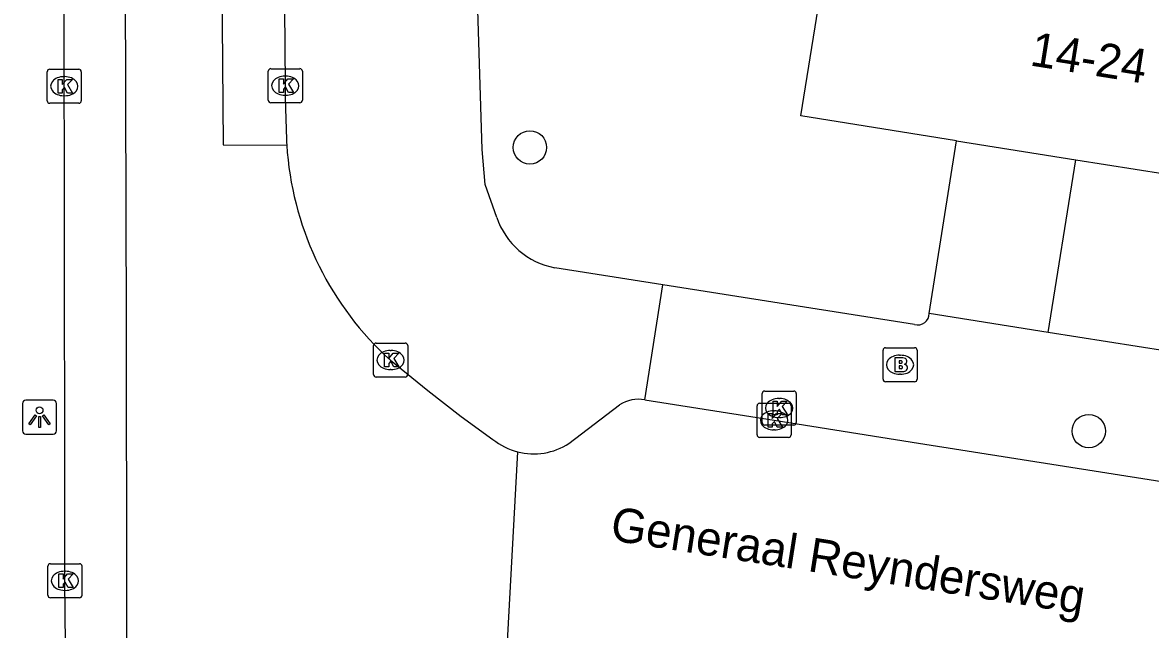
# Model space of a CAD drawing. Extents: x 161084 to 161928, y 385355 to 386522.
# Drawn here: x 161636.34 to 161669.44, y 385406.41 to 385424.21 of the extents above; entities that cross this region are included whole.
import ezdxf

# ---------------------------------------------------------------- set-up
doc = ezdxf.new("R2010")
doc.units = 0
for name, color, linetype in [('IMGEO_Boom', 7, 'Continuous'), ('IMGEO_Brandkraan', 7, 'Continuous'), ('IMGEO_Fietspad_gesloten', 7, 'Continuous'), ('IMGEO_Kolk', 7, 'Continuous'), ('IMGEO_Lichtpunt', 7, 'Continuous'), ('IMGEO_Openbare_ruimte_label', 7, 'Continuous'), ('IMGEO_Pand', 7, 'Continuous'), ('IMGEO_Pand_nummerreeks', 7, 'Continuous'), ('IMGEO_Rijbaan_lokaal_gesloten', 7, 'Continuous'), ('IMGEO_Rijbaan_lokaal_open', 7, 'Continuous'), ('IMGEO_Voetpad_open', 7, 'Continuous')]:
    doc.layers.add(name, color=color, linetype=linetype)

msp = doc.modelspace()

# ---------------------------------------------------------------- linework, layer by layer
at = {"layer": 'IMGEO_Boom'}
for centre in [(161651.233, 385420.546), (161667.63, 385412.225)]:
    msp.add_circle(centre, 0.489, dxfattribs=at)
at = {"layer": 'IMGEO_Brandkraan'}
for p, q in [((161661.594, 385413.744), (161661.594, 385414.596)), ((161661.669, 385414.67), (161662.521, 385414.67)), ((161662.082, 385414.45), (161662.107, 385414.45)), ((161662.595, 385414.596), (161662.595, 385413.744)), ((161662.105, 385413.89), (161662.08, 385413.89)), ((161662.521, 385413.67), (161661.669, 385413.67))]:
    msp.add_line(p, q, dxfattribs=at)
for points in [[(161661.594, 385413.744), (161661.594, 385414.596)], [(161661.669, 385414.67), (161662.521, 385414.67)], [(161661.942, 385414.37), (161661.942, 385413.97), (161662.155, 385413.97)], [(161662.173, 385414.37), (161661.942, 385414.37)], [(161662.595, 385414.596), (161662.595, 385413.744)], [(161662.121, 385414.289), (161662.067, 385414.289), (161662.067, 385414.213)], [(161662.067, 385414.213), (161662.12, 385414.213)], [(161662.129, 385414.137), (161662.067, 385414.137), (161662.067, 385414.056)], [(161662.067, 385414.056), (161662.129, 385414.056)], [(161662.521, 385413.67), (161661.669, 385413.67)]]:
    msp.add_lwpolyline(points, dxfattribs=at)
for centre, radius, start, end in [((161661.671, 385414.594), 0.0765, 91.552, 178.448), ((161661.671, 385414.594), 0.0765, 91.552, 178.448), ((161662.177, 385414.225), 0.145, 59.4692, 91.5367), ((161662.519, 385414.594), 0.0765, 1.552, 88.448), ((161662.519, 385414.594), 0.0765, 1.552, 88.448), ((161662.122, 385414.251), 0.0379, 267.8285, 90.9355), ((161662.13, 385414.096), 0.0404, 269.8759, 90.5077), ((161662.202, 385414.272), 0.0922, 285.5137, 58.1501), ((161662.207, 385414.08), 0.105, 301.3115, 78.989), ((161661.671, 385413.746), 0.0765, 181.552, 268.448), ((161661.671, 385413.746), 0.0765, 181.552, 268.448), ((161662.161, 385414.221), 0.251, 268.6676, 293.5347), ((161662.519, 385413.746), 0.0765, 271.552, 358.448), ((161662.519, 385413.746), 0.0765, 271.552, 358.448)]:
    msp.add_arc(centre, radius, start, end, dxfattribs=at)
for centre, major_axis, ratio, start_param, end_param in [((161662.081, 385414.17), (-0.387, 0.002), 0.722429, 4.712389, 7.853982), ((161662.106, 385414.17), (-0.39, 0.002), 0.717154, 1.570796, 4.712389)]:
    msp.add_ellipse(centre, major_axis=major_axis, ratio=ratio, start_param=start_param, end_param=end_param, dxfattribs=at)
at = {"layer": 'IMGEO_Fietspad_gesloten'}
for points in [[(161637.604, 385404.614), (161637.589, 385404.787), (161637.6, 385405.961), (161637.587, 385407.832), (161637.573, 385420.761), (161637.56, 385421.972), (161637.567, 385422.343), (161637.552, 385439.789), (161637.549, 385442.052)], [(161643.92, 385441.991), (161643.912, 385441.776), (161643.897, 385440.551), (161644.054, 385422.357), (161644.051, 385421.992), (161644.086, 385420.778), (161644.09, 385420.697), (161644.095, 385420.617)]]:
    msp.add_lwpolyline(points, dxfattribs=at)
at = {"layer": 'IMGEO_Kolk'}
for p, q in [((161637.066, 385421.917), (161637.066, 385422.769)), ((161637.141, 385422.843), (161637.993, 385422.843)), ((161638.067, 385422.769), (161638.067, 385421.917)), ((161643.553, 385421.931), (161643.553, 385422.783)), ((161643.628, 385422.857), (161644.48, 385422.857)), ((161644.041, 385422.637), (161644.066, 385422.637)), ((161644.554, 385422.783), (161644.554, 385421.931)), ((161637.554, 385422.623), (161637.579, 385422.623)), ((161637.577, 385422.063), (161637.552, 385422.063)), ((161644.064, 385422.077), (161644.039, 385422.077)), ((161637.993, 385421.843), (161637.141, 385421.843)), ((161644.48, 385421.857), (161643.628, 385421.857)), ((161646.644, 385413.881), (161646.644, 385414.733)), ((161646.719, 385414.807), (161647.571, 385414.807)), ((161647.645, 385414.733), (161647.645, 385413.881)), ((161647.132, 385414.587), (161647.157, 385414.587)), ((161647.155, 385414.027), (161647.13, 385414.027)), ((161647.571, 385413.807), (161646.719, 385413.807)), ((161658.121, 385413.399), (161658.973, 385413.399)), ((161657.973, 385413.041), (161658.825, 385413.041)), ((161658.046, 385412.473), (161658.046, 385413.325)), ((161658.534, 385413.179), (161658.559, 385413.179)), ((161659.047, 385413.325), (161659.047, 385412.473)), ((161657.898, 385412.115), (161657.898, 385412.967)), ((161658.386, 385412.821), (161658.411, 385412.821)), ((161658.899, 385412.967), (161658.899, 385412.115)), ((161658.973, 385412.399), (161658.121, 385412.399)), ((161658.557, 385412.619), (161658.532, 385412.619)), ((161658.825, 385412.041), (161657.973, 385412.041)), ((161658.409, 385412.261), (161658.384, 385412.261)), ((161637.086, 385407.406), (161637.086, 385408.258)), ((161637.161, 385408.332), (161638.013, 385408.332)), ((161637.574, 385408.112), (161637.599, 385408.112)), ((161638.087, 385408.258), (161638.087, 385407.406)), ((161637.597, 385407.552), (161637.572, 385407.552)), ((161638.013, 385407.332), (161637.161, 385407.332))]:
    msp.add_line(p, q, dxfattribs=at)
for points in [[(161637.066, 385421.917), (161637.066, 385422.769)], [(161637.141, 385422.843), (161637.993, 385422.843)], [(161638.067, 385422.769), (161638.067, 385421.917)], [(161643.553, 385421.931), (161643.553, 385422.783)], [(161643.628, 385422.857), (161644.48, 385422.857)], [(161644.554, 385422.783), (161644.554, 385421.931)], [(161637.387, 385422.543), (161637.51, 385422.543), (161637.51, 385422.392), (161637.64, 385422.543), (161637.804, 385422.543), (161637.658, 385422.392), (161637.811, 385422.143), (161637.659, 385422.143), (161637.574, 385422.307), (161637.51, 385422.24), (161637.51, 385422.143), (161637.387, 385422.143), (161637.387, 385422.543)], [(161643.874, 385422.557), (161643.997, 385422.557), (161643.997, 385422.406), (161644.127, 385422.557), (161644.291, 385422.557), (161644.145, 385422.406), (161644.298, 385422.157), (161644.146, 385422.157), (161644.061, 385422.321), (161643.997, 385422.254), (161643.997, 385422.157), (161643.874, 385422.157), (161643.874, 385422.557)], [(161637.993, 385421.843), (161637.141, 385421.843)], [(161644.48, 385421.857), (161643.628, 385421.857)], [(161646.644, 385413.881), (161646.644, 385414.733)], [(161646.719, 385414.807), (161647.571, 385414.807)], [(161647.645, 385414.733), (161647.645, 385413.881)], [(161646.965, 385414.507), (161647.088, 385414.507), (161647.088, 385414.356), (161647.218, 385414.507), (161647.382, 385414.507), (161647.236, 385414.356), (161647.389, 385414.107), (161647.237, 385414.107), (161647.152, 385414.271), (161647.088, 385414.204), (161647.088, 385414.107), (161646.965, 385414.107), (161646.965, 385414.507)], [(161647.571, 385413.807), (161646.719, 385413.807)], [(161658.121, 385413.399), (161658.973, 385413.399)], [(161657.973, 385413.041), (161658.825, 385413.041)], [(161658.046, 385412.473), (161658.046, 385413.325)], [(161658.367, 385413.099), (161658.49, 385413.099), (161658.49, 385412.948), (161658.62, 385413.099), (161658.784, 385413.099), (161658.638, 385412.948), (161658.791, 385412.699), (161658.639, 385412.699), (161658.554, 385412.863), (161658.49, 385412.796), (161658.49, 385412.699), (161658.367, 385412.699), (161658.367, 385413.099)], [(161659.047, 385413.325), (161659.047, 385412.473)], [(161657.898, 385412.115), (161657.898, 385412.967)], [(161658.219, 385412.741), (161658.342, 385412.741), (161658.342, 385412.59), (161658.472, 385412.741), (161658.636, 385412.741), (161658.49, 385412.59), (161658.643, 385412.341), (161658.491, 385412.341), (161658.406, 385412.505), (161658.342, 385412.438), (161658.342, 385412.341), (161658.219, 385412.341), (161658.219, 385412.741)], [(161658.899, 385412.967), (161658.899, 385412.115)], [(161658.973, 385412.399), (161658.121, 385412.399)], [(161658.825, 385412.041), (161657.973, 385412.041)], [(161637.086, 385407.406), (161637.086, 385408.258)], [(161637.161, 385408.332), (161638.013, 385408.332)], [(161638.087, 385408.258), (161638.087, 385407.406)], [(161637.407, 385408.032), (161637.53, 385408.032), (161637.53, 385407.881), (161637.66, 385408.032), (161637.824, 385408.032), (161637.678, 385407.881), (161637.831, 385407.632), (161637.679, 385407.632), (161637.594, 385407.796), (161637.53, 385407.729), (161637.53, 385407.632), (161637.407, 385407.632), (161637.407, 385408.032)], [(161638.013, 385407.332), (161637.161, 385407.332)]]:
    msp.add_lwpolyline(points, dxfattribs=at)
for centre, start, end in [((161637.143, 385422.767), 91.552, 178.448), ((161637.143, 385422.767), 91.552, 178.448), ((161637.991, 385422.767), 1.552, 88.448), ((161637.991, 385422.767), 1.552, 88.448), ((161643.63, 385422.781), 91.552, 178.448), ((161643.63, 385422.781), 91.552, 178.448), ((161644.478, 385422.781), 1.552, 88.448), ((161644.478, 385422.781), 1.552, 88.448), ((161637.143, 385421.919), 181.552, 268.448), ((161637.143, 385421.919), 181.552, 268.448), ((161637.991, 385421.919), 271.552, 358.448), ((161637.991, 385421.919), 271.552, 358.448), ((161643.63, 385421.933), 181.552, 268.448), ((161643.63, 385421.933), 181.552, 268.448), ((161644.478, 385421.933), 271.552, 358.448), ((161644.478, 385421.933), 271.552, 358.448), ((161646.721, 385414.731), 91.552, 178.448), ((161646.721, 385414.731), 91.552, 178.448), ((161647.569, 385414.731), 1.552, 88.448), ((161647.569, 385414.731), 1.552, 88.448), ((161646.721, 385413.883), 181.552, 268.448), ((161646.721, 385413.883), 181.552, 268.448), ((161647.569, 385413.883), 271.552, 358.448), ((161647.569, 385413.883), 271.552, 358.448), ((161658.123, 385413.323), 91.552, 178.448), ((161658.123, 385413.323), 91.552, 178.448), ((161658.971, 385413.323), 1.552, 88.448), ((161658.971, 385413.323), 1.552, 88.448), ((161657.975, 385412.965), 91.552, 178.448), ((161657.975, 385412.965), 91.552, 178.448), ((161658.823, 385412.965), 1.552, 88.448), ((161658.823, 385412.965), 1.552, 88.448), ((161658.123, 385412.475), 181.552, 268.448), ((161658.123, 385412.475), 181.552, 268.448), ((161658.971, 385412.475), 271.552, 358.448), ((161658.971, 385412.475), 271.552, 358.448), ((161657.975, 385412.117), 181.552, 268.448), ((161657.975, 385412.117), 181.552, 268.448), ((161658.823, 385412.117), 271.552, 358.448), ((161658.823, 385412.117), 271.552, 358.448), ((161637.163, 385408.256), 91.552, 178.448), ((161637.163, 385408.256), 91.552, 178.448), ((161638.011, 385408.256), 1.552, 88.448), ((161638.011, 385408.256), 1.552, 88.448), ((161637.163, 385407.408), 181.552, 268.448), ((161637.163, 385407.408), 181.552, 268.448), ((161638.011, 385407.408), 271.552, 358.448), ((161638.011, 385407.408), 271.552, 358.448)]:
    msp.add_arc(centre, 0.0765, start, end, dxfattribs=at)
for centre, major_axis, ratio, start_param, end_param in [((161644.04, 385422.357), (-0.387, 0.002), 0.722429, 4.712389, 7.853982), ((161644.065, 385422.357), (-0.39, 0.002), 0.717154, 1.570796, 4.712389), ((161637.553, 385422.343), (-0.387, 0.002), 0.722429, 4.712389, 7.853982), ((161637.578, 385422.343), (-0.39, 0.002), 0.717154, 1.570796, 4.712389), ((161647.131, 385414.307), (-0.387, 0.002), 0.722429, 4.712389, 7.853982), ((161647.156, 385414.307), (-0.39, 0.002), 0.717154, 1.570796, 4.712389), ((161658.533, 385412.899), (-0.387, 0.002), 0.722429, 4.712389, 7.853982), ((161658.558, 385412.899), (-0.39, 0.002), 0.717154, 1.570796, 4.712389), ((161658.385, 385412.541), (-0.387, 0.002), 0.722429, 4.712389, 7.853982), ((161658.41, 385412.541), (-0.39, 0.002), 0.717154, 1.570796, 4.712389), ((161637.573, 385407.832), (-0.387, 0.002), 0.722429, 4.712389, 7.853982), ((161637.598, 385407.832), (-0.39, 0.002), 0.717154, 1.570796, 4.712389)]:
    msp.add_ellipse(centre, major_axis=major_axis, ratio=ratio, start_param=start_param, end_param=end_param, dxfattribs=at)
at = {"layer": 'IMGEO_Lichtpunt'}
for p, q in [((161636.343, 385413.036), (161636.343, 385412.229)), ((161636.343, 385413.036), (161636.343, 385412.229)), ((161637.245, 385413.131), (161636.437, 385413.131)), ((161637.245, 385413.131), (161636.437, 385413.131)), ((161637.339, 385412.229), (161637.339, 385413.036)), ((161637.339, 385412.229), (161637.339, 385413.036)), ((161636.437, 385412.135), (161637.245, 385412.135)), ((161636.437, 385412.135), (161637.245, 385412.135))]:
    msp.add_line(p, q, dxfattribs=at)
for points in [[(161636.717, 385412.7), (161636.756, 385412.672), (161636.568, 385412.41), (161636.53, 385412.437), (161636.717, 385412.7)], [(161636.819, 385412.652), (161636.866, 385412.652), (161636.866, 385412.33), (161636.819, 385412.33), (161636.819, 385412.652)], [(161636.929, 385412.672), (161636.967, 385412.699), (161637.154, 385412.437), (161637.115, 385412.409), (161636.929, 385412.672)]]:
    msp.add_lwpolyline(points, dxfattribs=at)
msp.add_circle((161636.842, 385412.834), 0.0994, dxfattribs=at)
for centre, start, end in [((161636.437, 385413.036), 90, 180), ((161636.437, 385413.036), 90, 180), ((161637.245, 385413.036), 0, 90), ((161637.245, 385413.036), 0, 90), ((161636.437, 385412.229), 180, 270), ((161636.437, 385412.229), 180, 270), ((161637.245, 385412.229), 270, 0), ((161637.245, 385412.229), 270, 360)]:
    msp.add_arc(centre, 0.0946, start, end, dxfattribs=at)
at = {"layer": 'IMGEO_Pand'}
for points in [[(161663.754, 385420.742), (161659.187, 385421.469), (161659.876, 385425.794), (161660.033, 385426.782), (161660.765, 385431.379), (161668.52, 385430.144), (161669.679, 385429.959), (161678.593, 385428.539)], [(161663.754, 385420.742), (161667.25, 385420.185)], [(161667.25, 385420.185), (161670.73, 385419.631)]]:
    msp.add_lwpolyline(points, dxfattribs=at)
at = {"layer": 'IMGEO_Rijbaan_lokaal_gesloten'}
for points in [[(161639.301, 385442.036), (161639.382, 385415.385), (161639.401, 385399.233), (161639.539, 385386.001)], [(161642.051, 385442.009), (161642.23, 385420.626), (161644.095, 385420.617)], [(161646.973, 385414.451), (161647.145, 385414.307), (161648.235, 385413.414), (161649.214, 385412.655), (161650.147, 385411.981)], [(161650.872, 385411.617), (161650.511, 385405.15)]]:
    msp.add_lwpolyline(points, dxfattribs=at)
for centre, radius, start, end in [((161653.409, 385421.21), 9.333, 183.642, 226.3999), ((161651.346, 385413.466), 1.908, 231.0691, 255.6113)]:
    msp.add_arc(centre, radius, start, end, dxfattribs=at)
at = {"layer": 'IMGEO_Rijbaan_lokaal_open'}
for points in [[(161654.604, 385413.143), (161658.399, 385412.541), (161662.632, 385411.873), (161671.022, 385410.55), (161693.625, 385407.334)], [(161652.376, 385411.86), (161653.86, 385412.994)]]:
    msp.add_lwpolyline(points, dxfattribs=at)
for centre, radius, start, end in [((161654.427, 385412.094), 1.064, 80.4256, 122.2238), ((161651.345, 385413.466), 1.909, 255.6552, 302.7006)]:
    msp.add_arc(centre, radius, start, end, dxfattribs=at)
at = {"layer": 'IMGEO_Voetpad_open'}
for points in [[(161650.258, 385418.495), (161649.92, 385419.461), (161649.827, 385420.482), (161649.613, 385427.428), (161649.582, 385428.447), (161649.507, 385430.881), (161649.459, 385432.447)], [(161662.949, 385415.678), (161663.754, 385420.742)], [(161666.445, 385415.121), (161667.25, 385420.185)], [(161655.13, 385416.518), (161651.959, 385417.017)], [(161654.604, 385413.143), (161655.13, 385416.518)], [(161662.521, 385415.355), (161655.13, 385416.518)], [(161666.445, 385415.121), (161662.949, 385415.678)], [(161669.924, 385414.566), (161666.445, 385415.121)]]:
    msp.add_lwpolyline(points, dxfattribs=at)
for centre, radius, start, end in [((161652.374, 385419.213), 2.234, 198.7314, 259.2938), ((161662.617, 385415.673), 0.332, 253.2397, 0.8421)]:
    msp.add_arc(centre, radius, start, end, dxfattribs=at)

# ---------------------------------------------------------------- texts
at = {"layer": 'IMGEO_Openbare_ruimte_label'}
msp.add_text('Generaal Reyndersweg', height=1, rotation=351.084, dxfattribs=at).set_placement((161653.558, 385409.03))
at = {"layer": 'IMGEO_Pand_nummerreeks'}
msp.add_text('14-24', height=1, rotation=350.952, dxfattribs=at).set_placement((161665.876, 385422.956))

doc.saveas('drawing.dxf')
